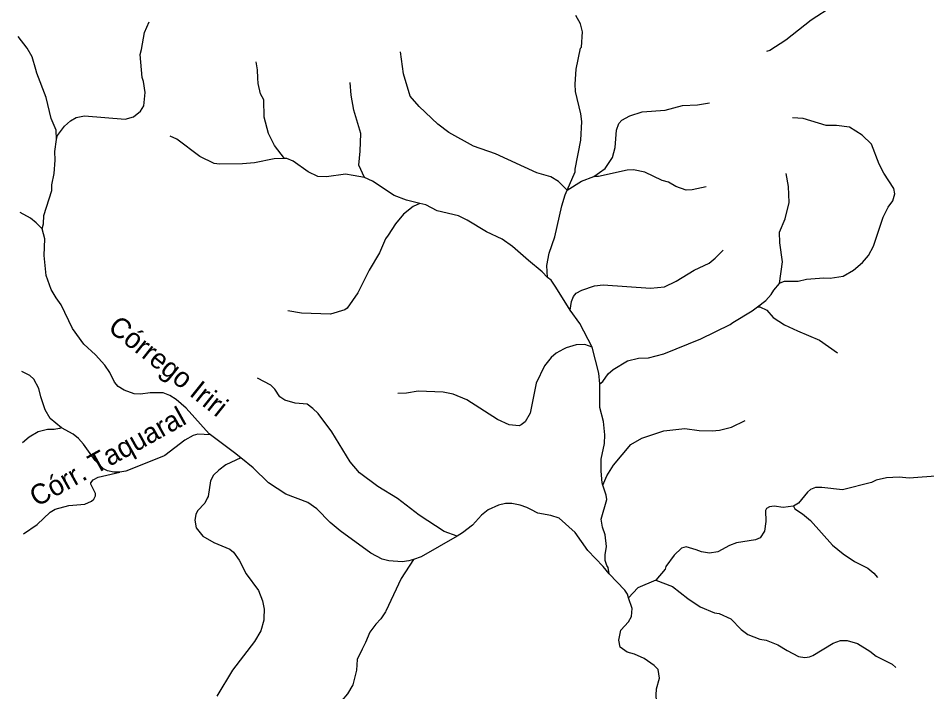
# Model space of a CAD drawing. Extents: x 317.8 to 344.1, y 7676.8 to 7704.8.
# Drawn here: x 317.84 to 321.463, y 7697.725 to 7700.411 of the extents above; entities that cross this region are included whole.
import ezdxf
from ezdxf.enums import TextEntityAlignment as Align

# ---------------------------------------------------------------- set-up
doc = ezdxf.new("R2010")
doc.units = 0
doc.header["$LTSCALE"] = 0.032
doc.layers.add('61', color=7, linetype='Continuous')
doc.layers.add('7', color=7, linetype='Continuous', lineweight=25)

msp = doc.modelspace()

# ---------------------------------------------------------------- linework, layer by layer
at = {"layer": '7'}
for points in [[(321.1825, 7700.4923), (321.1352, 7700.4814), (321.0885, 7700.4585), (321.0025, 7700.4033), (320.9015, 7700.3228), (320.8374, 7700.2814), (320.8234, 7700.2775)], [(320.0295, 7699.7254), (320.0611, 7699.7979), (320.0605, 7699.8085), (320.0832, 7699.9237), (320.088, 7699.9994), (320.084, 7700.0297), (320.062, 7700.1177), (320.0604, 7700.1479), (320.0654, 7700.2077), (320.0825, 7700.2911), (320.0858, 7700.2953), (320.0897, 7700.3564), (320.0824, 7700.3883), (320.0632, 7700.4208)], [(317.9925, 7699.9271), (317.9971, 7699.9425), (318.0243, 7699.9805), (318.0484, 7700.0009), (318.0707, 7700.0149), (318.1039, 7700.0207), (318.2662, 7700.008), (318.2995, 7700.0172), (318.3281, 7700.0406), (318.3409, 7700.0607), (318.3457, 7700.1148), (318.3393, 7700.1578), (318.3335, 7700.1748), (318.3256, 7700.2656), (318.3318, 7700.2856), (318.3436, 7700.3535), (318.362, 7700.3957)], [(317.9925, 7699.9271), (317.9912, 7699.9638), (317.9709, 7700.0102), (317.9513, 7700.0946), (317.9135, 7700.1917), (317.9097, 7700.2058), (317.896, 7700.2572), (317.8749, 7700.2917), (317.8397, 7700.3371)], [(320.0295, 7699.7254), (319.9947, 7699.7597), (319.9635, 7699.7786), (319.908, 7699.7941), (319.7431, 7699.8693), (319.6558, 7699.8999), (319.5574, 7699.955), (319.5126, 7699.9876), (319.4383, 7700.0584), (319.4029, 7700.0996), (319.3757, 7700.1885), (319.3637, 7700.2767)], [(318.9024, 7699.8516), (318.8624, 7699.9028), (318.8376, 7699.9504), (318.8209, 7700.0166), (318.8191, 7700.0853), (318.8057, 7700.109), (318.7963, 7700.1506), (318.7954, 7700.1717), (318.7939, 7700.2041), (318.7883, 7700.236)], [(319.2209, 7699.7761), (319.1982, 7699.8242), (319.2038, 7699.8811), (319.2055, 7699.9514), (319.1787, 7700.044), (319.1681, 7700.104), (319.1632, 7700.1545)], [(320.1347, 7699.7794), (320.1808, 7699.8113), (320.2093, 7699.855), (320.22, 7699.8953), (320.2259, 7699.9645), (320.235, 7699.9904), (320.247, 7700.0041), (320.2786, 7700.0218), (320.328, 7700.0369), (320.4202, 7700.0436), (320.4894, 7700.0629), (320.5489, 7700.0648), (320.5968, 7700.0738)], [(320.8763, 7699.3535), (320.8778, 7699.3553), (320.8956, 7699.3621), (320.9499, 7699.3622), (320.9838, 7699.3705), (321.0523, 7699.3752), (321.0775, 7699.3736), (321.13, 7699.3816), (321.1703, 7699.4058), (321.2063, 7699.4371), (321.2304, 7699.4651), (321.2509, 7699.5012), (321.2891, 7699.6177), (321.3089, 7699.6577), (321.3277, 7699.6826), (321.3352, 7699.711), (321.3322, 7699.7321), (321.2913, 7699.7931), (321.2725, 7699.8289), (321.2422, 7699.9082), (321.2057, 7699.9442), (321.1554, 7699.9757), (321.1035, 7699.9832), (321.0624, 7699.9824), (320.9698, 7700.0101), (320.9277, 7700.0135)], [(318.9024, 7699.8516), (318.8606, 7699.8504), (318.782, 7699.8341), (318.7339, 7699.8301), (318.6425, 7699.8284), (318.6207, 7699.8316), (318.5642, 7699.8588), (318.4718, 7699.928), (318.4452, 7699.9409)], [(317.9352, 7699.5705), (317.9405, 7699.5905), (317.9423, 7699.6238), (317.9733, 7699.724), (317.9733, 7699.7461), (317.9828, 7699.7914), (317.9878, 7699.8452), (317.9863, 7699.8794), (317.9925, 7699.9271)], [(319.2209, 7699.7761), (319.1756, 7699.7835), (319.1456, 7699.7884), (319.069, 7699.7785), (319.0348, 7699.7797), (318.9959, 7699.7978), (318.9362, 7699.8407), (318.911, 7699.8518), (318.9024, 7699.8516)], [(320.5838, 7699.7388), (320.5276, 7699.7257), (320.5034, 7699.7256), (320.4627, 7699.7395), (320.4326, 7699.7568), (320.4082, 7699.7641), (320.3391, 7699.7963), (320.2931, 7699.8055), (320.2677, 7699.8054), (320.154, 7699.7795), (320.1347, 7699.7794)], [(319.4418, 7699.6721), (319.3884, 7699.6856), (319.3396, 7699.7044), (319.2533, 7699.7606), (319.2209, 7699.7761)], [(320.0295, 7699.7254), (320.0861, 7699.7607), (320.1347, 7699.7794)], [(320.8763, 7699.3535), (320.8763, 7699.3536), (320.8877, 7699.4393), (320.8766, 7699.515), (320.8753, 7699.5575), (320.8984, 7699.6108), (320.9145, 7699.6754), (320.9121, 7699.7395), (320.9024, 7699.791)], [(319.9504, 7699.3764), (319.9475, 7699.4245), (319.9569, 7699.474), (319.9796, 7699.5387), (320.0074, 7699.662), (320.021, 7699.7059), (320.0295, 7699.7254)], [(319.4418, 7699.6721), (319.4149, 7699.6596), (319.3769, 7699.629), (319.3444, 7699.5914), (319.3148, 7699.546), (319.3048, 7699.5306), (319.2804, 7699.4747), (319.2397, 7699.4061), (319.1944, 7699.3156), (319.1519, 7699.2551), (319.1425, 7699.2485), (319.0852, 7699.2302), (318.9699, 7699.2351), (318.9146, 7699.2441)], [(319.9504, 7699.3764), (319.929, 7699.3991), (319.8749, 7699.4441), (319.8116, 7699.5011), (319.7695, 7699.5292), (319.7072, 7699.5588), (319.63, 7699.6054), (319.5957, 7699.6226), (319.5106, 7699.6425), (319.4657, 7699.666), (319.4418, 7699.6721)], [(317.9352, 7699.5705), (317.9113, 7699.5952), (317.8883, 7699.6131), (317.8473, 7699.6366)], [(318.6066, 7698.7496), (318.6011, 7698.7537), (318.5101, 7698.8562), (318.4697, 7698.8899), (318.444, 7698.9059), (318.4179, 7698.9171), (318.3657, 7698.9171), (318.3273, 7698.9115), (318.3029, 7698.9136), (318.2625, 7698.9282), (318.2381, 7698.9419), (318.2239, 7698.9594), (318.2048, 7698.9976), (318.1859, 7699.0272), (318.1482, 7699.0682), (318.1017, 7699.1114), (318.056, 7699.1736), (318.0108, 7699.2682), (317.9907, 7699.2952), (317.9712, 7699.3294), (317.9507, 7699.3845), (317.9431, 7699.4652), (317.9454, 7699.5306), (317.9352, 7699.5705)], [(320.0407, 7699.2469), (320.0457, 7699.2812), (320.0543, 7699.3007), (320.0654, 7699.314), (320.087, 7699.327), (320.1378, 7699.343), (320.1731, 7699.3475), (320.3618, 7699.3345), (320.4168, 7699.3394), (320.4633, 7699.3623), (320.5359, 7699.4063), (320.5946, 7699.4341), (320.6198, 7699.4537), (320.6506, 7699.4861)], [(320.0407, 7699.2469), (319.9844, 7699.3388), (319.9647, 7699.3656), (319.9504, 7699.3764)], [(320.7883, 7699.2604), (320.8206, 7699.2857), (320.843, 7699.3095), (320.8534, 7699.3269), (320.8763, 7699.3535)], [(320.159, 7698.9528), (320.1709, 7698.9623), (320.1922, 7698.9927), (320.2126, 7699.0107), (320.2696, 7699.045), (320.3136, 7699.0557), (320.3533, 7699.0566), (320.4139, 7699.0732), (320.5615, 7699.1323), (320.6785, 7699.19), (320.6898, 7699.1969), (320.7668, 7699.2435), (320.7883, 7699.2604)], [(320.7883, 7699.2604), (320.7978, 7699.2603), (320.8246, 7699.2469), (320.85, 7699.2178), (320.8962, 7699.1885), (320.9476, 7699.1636), (321.0358, 7699.1276), (321.107, 7699.077)], [(320.1292, 7699.0994), (320.0789, 7699.1939), (320.0407, 7699.2469)], [(320.1292, 7699.0994), (320.0997, 7699.1104), (320.0646, 7699.1083), (320.0254, 7699.0964), (320.014, 7699.0905), (319.9846, 7699.0753), (319.9654, 7699.0577), (319.9387, 7699.025), (319.9049, 7698.9558), (319.8818, 7698.8362), (319.8614, 7698.802), (319.8458, 7698.7889), (319.8376, 7698.7859), (319.7976, 7698.79), (319.7513, 7698.8106), (319.6293, 7698.8894), (319.5738, 7698.9118), (319.5348, 7698.9196), (319.4353, 7698.9237), (319.3884, 7698.9156), (319.3531, 7698.9148)], [(320.159, 7698.9528), (320.1559, 7698.9959), (320.1292, 7699.0994)], [(318.0123, 7698.7774), (317.9676, 7698.8153), (317.9475, 7698.8491), (317.9295, 7698.9006), (317.9224, 7698.935), (317.9026, 7698.972), (317.8865, 7698.9858), (317.8542, 7699.0023)], [(319.59, 7698.3459), (319.5385, 7698.3637), (319.4388, 7698.4295), (319.3521, 7698.4962), (319.2736, 7698.544), (319.2002, 7698.5983), (319.1636, 7698.6419), (319.0903, 7698.7618), (319.0357, 7698.8343), (319.0151, 7698.855), (318.9917, 7698.8724), (318.9444, 7698.8757), (318.9034, 7698.8878), (318.8837, 7698.9009), (318.8636, 7698.9316), (318.8474, 7698.9477), (318.794, 7698.9759)], [(320.1713, 7698.5488), (320.1679, 7698.5589), (320.1639, 7698.6043), (320.164, 7698.6523), (320.1777, 7698.7152), (320.1794, 7698.7493), (320.1737, 7698.8023), (320.1589, 7698.8589), (320.159, 7698.9528)], [(320.1713, 7698.5488), (320.1871, 7698.586), (320.2142, 7698.6286), (320.2835, 7698.7107), (320.3269, 7698.7362), (320.415, 7698.7655), (320.4979, 7698.7746), (320.5557, 7698.7672), (320.6076, 7698.7655), (320.6364, 7698.7688), (320.6837, 7698.7807), (320.7386, 7698.8064)], [(318.0123, 7698.7774), (318.0047, 7698.7752), (317.9835, 7698.7706), (317.9566, 7698.7704), (317.9199, 7698.7622), (317.883, 7698.7397), (317.8573, 7698.7177)], [(318.2451, 7698.6006), (318.2207, 7698.6008), (318.1959, 7698.6059), (318.1799, 7698.6141), (318.1462, 7698.6477), (318.1006, 7698.7123), (318.0806, 7698.7349), (318.0593, 7698.7519), (318.0123, 7698.7774)], [(318.6066, 7698.7496), (318.5564, 7698.7517), (318.5369, 7698.7467), (318.5047, 7698.7279), (318.4247, 7698.6669), (318.4186, 7698.6645), (318.2693, 7698.6049), (318.2451, 7698.6006)], [(318.728, 7698.6579), (318.7028, 7698.6785), (318.6066, 7698.7496)], [(318.728, 7698.6579), (318.6679, 7698.6296), (318.6396, 7698.609), (318.6189, 7698.589), (318.6073, 7698.5659), (318.5974, 7698.5037), (318.5939, 7698.497), (318.5836, 7698.4775), (318.5553, 7698.4461), (318.5476, 7698.4318), (318.5446, 7698.4091), (318.5501, 7698.3788), (318.5761, 7698.3453), (318.6202, 7698.3205), (318.6843, 7698.2938), (318.698, 7698.282), (318.7209, 7698.2504), (318.7492, 7698.1956), (318.7979, 7698.1291), (318.8144, 7698.0876), (318.8208, 7698.0548), (318.8193, 7698.0183), (318.819, 7698.0114), (318.8069, 7697.9677), (318.7827, 7697.9256), (318.6943, 7697.8109), (318.6316, 7697.7081)], [(319.4162, 7698.2532), (319.3972, 7698.2471), (319.3713, 7698.2432), (319.3173, 7698.2473), (319.2907, 7698.2536), (319.2457, 7698.278), (319.1242, 7698.3667), (319.0841, 7698.3996), (319.0304, 7698.455), (318.9945, 7698.4794), (318.9074, 7698.5135), (318.8382, 7698.5585), (318.7771, 7698.6178), (318.728, 7698.6579)], [(317.8612, 7698.3553), (317.9159, 7698.3918), (317.9674, 7698.4413), (317.9876, 7698.4533), (318.0417, 7698.4673), (318.1055, 7698.4739), (318.1326, 7698.4851), (318.142, 7698.4927), (318.1476, 7698.506), (318.1475, 7698.5154), (318.1297, 7698.5529), (318.1299, 7698.5579), (318.139, 7698.5702), (318.1587, 7698.5804), (318.2451, 7698.6006)], [(321.5497, 7698.5777), (321.5155, 7698.5861), (321.3933, 7698.5766), (321.3529, 7698.5813), (321.3024, 7698.5782), (321.2613, 7698.5684), (321.2424, 7698.5592), (321.1273, 7698.5309), (321.0448, 7698.5395), (321.0199, 7698.5391), (320.9999, 7698.5311), (320.9869, 7698.5209), (320.9515, 7698.4773), (320.9312, 7698.4654)], [(320.1963, 7698.1953), (320.1931, 7698.2202), (320.1869, 7698.2286), (320.1803, 7698.2482), (320.1803, 7698.2717), (320.1859, 7698.3044), (320.1811, 7698.3504), (320.1696, 7698.3818), (320.1648, 7698.4131), (320.1869, 7698.4919), (320.1848, 7698.5091), (320.1713, 7698.5488)], [(320.1963, 7698.1953), (320.1729, 7698.2244), (320.1116, 7698.2882), (320.0604, 7698.3605), (319.9977, 7698.4175), (319.9634, 7698.4277), (319.9124, 7698.4375), (319.8841, 7698.4516), (319.8676, 7698.4598), (319.8413, 7698.4694), (319.8077, 7698.4754), (319.7825, 7698.4754), (319.7555, 7698.4699), (319.7135, 7698.4503), (319.6872, 7698.429), (319.6513, 7698.3899), (319.6122, 7698.3588), (319.59, 7698.3459)], [(320.9312, 7698.4654), (320.93, 7698.4653), (320.8904, 7698.4606), (320.8544, 7698.4655), (320.8361, 7698.4626), (320.8239, 7698.4556), (320.8195, 7698.4482), (320.8208, 7698.4039), (320.816, 7698.3657), (320.798, 7698.3395), (320.7804, 7698.3306), (320.7036, 7698.3197), (320.6764, 7698.3086), (320.6302, 7698.2826), (320.5965, 7698.2783), (320.5645, 7698.2826), (320.5436, 7698.2916), (320.503, 7698.3026), (320.4854, 7698.2979), (320.4562, 7698.2697), (320.4221, 7698.2244), (320.4198, 7698.2142), (320.3831, 7698.1708)], [(320.9312, 7698.4654), (320.9372, 7698.4546), (320.9673, 7698.4349), (320.9996, 7698.4076), (321.0871, 7698.3097), (321.1301, 7698.2746), (321.1742, 7698.2443), (321.2275, 7698.2186), (321.2515, 7698.1981), (321.2667, 7698.1805)], [(319.59, 7698.3459), (319.4474, 7698.2632), (319.4162, 7698.2532)], [(319.4162, 7698.2532), (319.367, 7698.1766), (319.3063, 7698.0473), (319.3042, 7698.044), (319.2858, 7698.0161), (319.2659, 7697.9953), (319.2425, 7697.9634), (319.2247, 7697.9215), (319.2113, 7697.8946), (319.1909, 7697.8538), (319.1892, 7697.8116), (319.174, 7697.7532), (319.1527, 7697.717), (319.131, 7697.69), (319.1202, 7697.6652), (319.1125, 7697.6242), (319.1141, 7697.5746), (319.1008, 7697.54), (319.0829, 7697.5143), (319.0776, 7697.4986), (319.0759, 7697.4662), (319.0783, 7697.427), (319.0702, 7697.357), (319.0801, 7697.3068)], [(320.2742, 7698.1005), (320.2699, 7698.1142), (320.2591, 7698.1302), (320.1963, 7698.1953)], [(320.3831, 7698.1708), (320.311, 7698.1398), (320.2742, 7698.1005)], [(320.3831, 7698.1708), (320.4492, 7698.1456), (320.5101, 7698.0971), (320.5592, 7698.0646), (320.6171, 7698.0403), (320.6353, 7698.0368), (320.6815, 7698.0156), (320.7233, 7697.974), (320.7492, 7697.953), (320.7977, 7697.9351), (320.8225, 7697.931), (320.8684, 7697.9128), (320.9057, 7697.8895), (320.9517, 7697.8665), (320.9771, 7697.8625), (320.9953, 7697.8642), (321.0081, 7697.8693), (321.0896, 7697.9195), (321.1195, 7697.9293), (321.1459, 7697.9293), (321.1866, 7697.9176), (321.2364, 7697.8869), (321.2615, 7697.8667), (321.3245, 7697.8356), (321.3401, 7697.8219)], [(320.2349, 7697.9315), (320.243, 7697.9703), (320.2742, 7698.0046), (320.2861, 7698.0257), (320.2878, 7698.0573), (320.2742, 7698.1005)], [(320.385, 7697.6894), (320.3833, 7697.7118), (320.385, 7697.7365), (320.397, 7697.779), (320.3919, 7697.8146), (320.3761, 7697.8297), (320.3364, 7697.8586), (320.2969, 7697.8759), (320.2688, 7697.8831), (320.2407, 7697.9027), (320.2349, 7697.9315)]]:
    msp.add_lwpolyline(points, dxfattribs=at)

# ---------------------------------------------------------------- texts
at = {"layer": '61'}
for s, rotation, p in [('Córrego Iriri', 321.429, (318.4139, 7698.9927)), ('Córr. Taquaral', 29.055, (318.2152, 7698.6284))]:
    msp.add_text(s, height=0.08, rotation=rotation, dxfattribs=at).set_placement(p, align=Align.CENTER)

doc.saveas('drawing.dxf')
